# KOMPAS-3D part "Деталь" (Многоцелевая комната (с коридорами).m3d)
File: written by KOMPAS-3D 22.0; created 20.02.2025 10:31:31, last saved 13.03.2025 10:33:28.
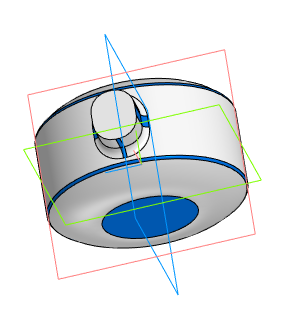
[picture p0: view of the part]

Document properties: Автор: Пользователь Windows; Полное имя файла: C:\Users\Student\Documents\Картошечка\База Сабнатика\Многоцелевая комната\Многоцелевая комната (с коридорами).m3d

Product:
- Body: Тело 1
    Масса: 0.420426
- Part/product: Деталь
    Масса: 0.435743

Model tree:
1. Эскиз:3
2. Элемент вращения:1
     Угол 1 = 360
3. Скругление:1  (with: Элемент вращения:1)
     Радиус = 1
4. Эскиз:4
5. Элемент выдавливания:1
     Расстояние 1 = 65
6. Скругление:2  (with: Элемент выдавливания:1)
     Радиус = 2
